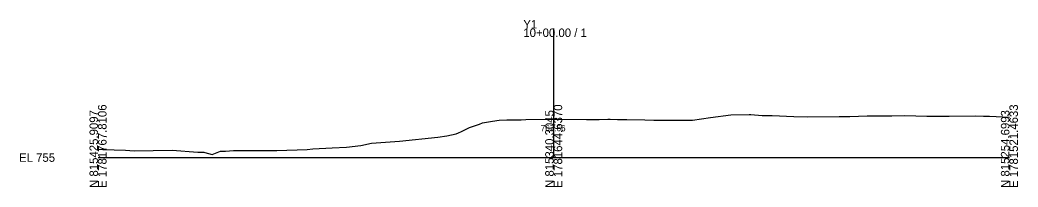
# Model space of a CAD drawing. Extents: x -26 to 3603, y -10 to 9847.
# Drawn here: x -25.7 to 302.8, y -9.7 to 45.3 of the extents above; entities that cross this region are included whole.
import ezdxf

# ---------------------------------------------------------------- set-up
doc = ezdxf.new("R2010")
doc.units = 0
for name, color, linetype in [('Exist Cross Section Cell', 7, 'Continuous'), ('Exist XS Center Line Elevation Label', 7, 'Continuous'), ('Exist XS Ground Line', 7, 'Continuous')]:
    doc.layers.add(name, color=color, linetype=linetype)

msp = doc.modelspace()

# ---------------------------------------------------------------- linework, layer by layer
at = {"layer": 'Exist Cross Section Cell'}
for p, q in [((150, 0), (150, 42.45)), ((0, 0), (150, 0)), ((150, 0), (300, 0))]:
    msp.add_line(p, q, dxfattribs=at)
at = {"layer": 'Exist XS Ground Line'}
for p, q in [((195.68, 12.25), (201.65, 13.21)), ((201.65, 13.21), (208.33, 14.02)), ((208.33, 14.02), (214.39, 14.15)), ((214.39, 14.15), (214.85, 14.15)), ((214.85, 14.15), (218.59, 13.86)), ((218.59, 13.86), (220.46, 13.8)), ((220.46, 13.8), (221.88, 13.79)), ((221.88, 13.79), (228.99, 13.54)), ((228.99, 13.54), (233.45, 13.34)), ((233.45, 13.34), (243.94, 13.5)), ((243.94, 13.5), (247.52, 13.55)), ((247.52, 13.55), (253.21, 13.7)), ((253.21, 13.7), (261.32, 13.72)), ((261.32, 13.72), (265.55, 13.84)), ((265.55, 13.84), (272.86, 13.58)), ((272.86, 13.58), (273.28, 13.59)), ((273.28, 13.59), (279.32, 13.63)), ((279.32, 13.63), (280.15, 13.62)), ((280.15, 13.62), (288.97, 13.69)), ((288.97, 13.69), (291.47, 13.64)), ((291.47, 13.64), (293.45, 13.61)), ((293.45, 13.61), (300, 13.31)), ((119.63, 8.52), (122.29, 9.87)), ((122.29, 9.87), (125.54, 10.98)), ((125.54, 10.98), (126.6, 11.38)), ((126.6, 11.38), (129.9, 11.92)), ((129.9, 11.92), (132.09, 12.31)), ((132.09, 12.31), (134.57, 12.45)), ((134.57, 12.45), (136.49, 12.45)), ((136.49, 12.45), (139.24, 12.46)), ((139.24, 12.46), (140.81, 12.48)), ((140.81, 12.48), (149.89, 12.66)), ((149.89, 12.66), (151.77, 12.64)), ((151.77, 12.64), (160.74, 12.56)), ((160.74, 12.56), (165, 12.56)), ((165, 12.56), (167.76, 12.6)), ((167.76, 12.6), (168.61, 12.61)), ((168.61, 12.61), (170.98, 12.56)), ((170.98, 12.56), (174.04, 12.51)), ((174.04, 12.51), (180.01, 12.38)), ((180.01, 12.38), (182.99, 12.33)), ((182.99, 12.33), (187.21, 12.29)), ((187.21, 12.29), (190.18, 12.28)), ((190.18, 12.28), (195.68, 12.25)), ((99.22, 5.35), (111.89, 6.66)), ((111.89, 6.66), (114.8, 7.12)), ((114.8, 7.12), (117.85, 7.82)), ((117.85, 7.82), (118.7, 8.14)), ((118.7, 8.14), (119.63, 8.52)), ((77.08, 3.25), (81.82, 3.46)), ((81.82, 3.46), (86.55, 3.99)), ((86.55, 3.99), (90.06, 4.7)), ((90.06, 4.7), (99.22, 5.35)), ((0, 2.76), (1.61, 2.66)), ((1.61, 2.66), (9.05, 2.4)), ((9.05, 2.4), (11.94, 2.26)), ((11.94, 2.26), (24.45, 2.47)), ((24.45, 2.47), (32.89, 1.76)), ((32.89, 1.76), (34.82, 1.75)), ((34.82, 1.75), (35.2, 1.65)), ((35.2, 1.65), (37.57, 1)), ((37.57, 1), (40.27, 2.13)), ((40.27, 2.13), (42, 2.14)), ((42, 2.14), (44.65, 2.31)), ((44.65, 2.31), (45.52, 2.32)), ((45.52, 2.32), (58.83, 2.35)), ((58.83, 2.35), (68.86, 2.63)), ((68.86, 2.63), (70.71, 2.87)), ((70.71, 2.87), (77.08, 3.25))]:
    msp.add_line(p, q, dxfattribs=at)

# ---------------------------------------------------------------- texts
at = {"layer": 'Exist Cross Section Cell'}
for s, p in [('Y1', (140, 42.45)), ('10+00.00 / 1', (140, 39.65)), ('EL 755', (-26, -1.4))]:
    msp.add_text(s, height=2.8, dxfattribs=at).set_placement(p)
for s, p in [('E 1781767.8106', (2.8, -10)), ('E 1781644.6370', (152.8, -10)), ('E 1781521.4633', (302.8, -10)), ('N 815425.9097', (0, -10)), ('N 815340.3045', (150, -10)), ('N 815254.6993', (300, -10))]:
    msp.add_text(s, height=2.8, rotation=90, dxfattribs=at).set_placement(p)
at = {"layer": 'Exist XS Center Line Elevation Label'}
msp.add_text('767.66', height=2, dxfattribs=at).set_placement((145.73, 8.66))

doc.saveas('drawing.dxf')
